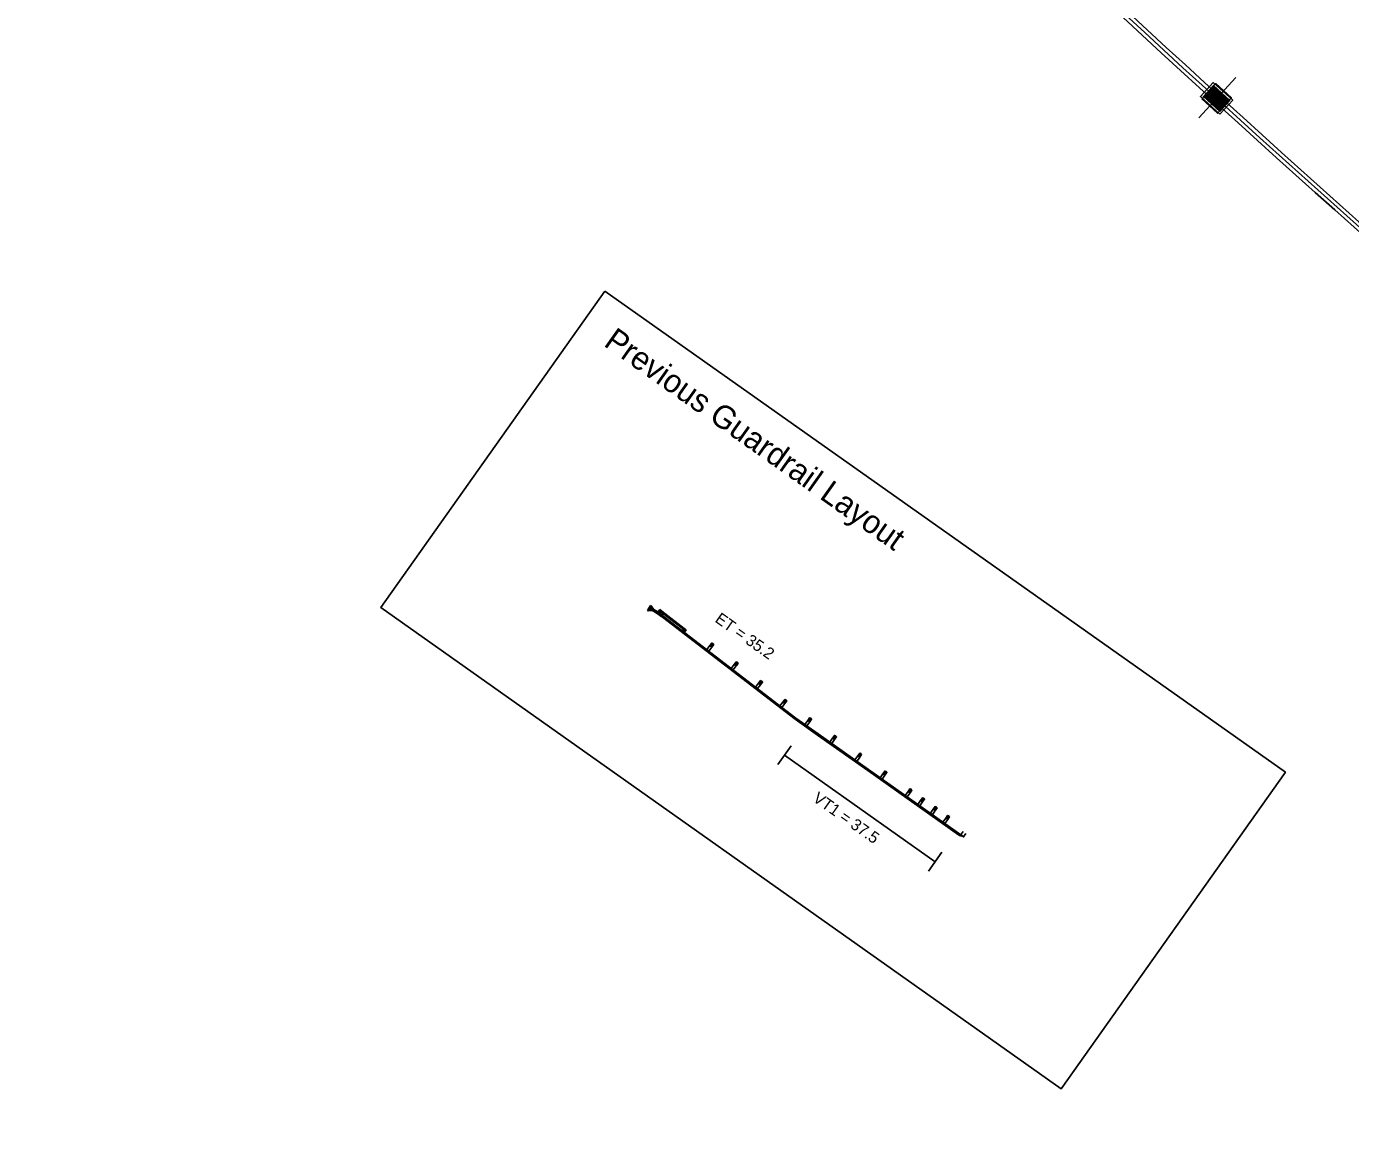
# Model space of a CAD drawing. Extents: x 16457860 to 16462445, y 6896068 to 6900243.
# Drawn here: x 16458321.9 to 16458590.6, y 6899787.1 to 6900015.1 of the extents above; entities that cross this region are included whole.
import ezdxf

# ---------------------------------------------------------------- set-up
doc = ezdxf.new("R2010")
doc.units = 0
for name, color, linetype in [('Barrier', 7, 'Continuous'), ('Draft_DNC', 7, 'Continuous'), ('RD Culv Reinf Concrete Sewer Pipe', 7, 'Continuous')]:
    doc.layers.add(name, color=color, linetype=linetype)

msp = doc.modelspace()

# ---------------------------------------------------------------- linework, layer by layer
at = {"layer": 'Barrier'}
for p, q in [((16458449.51, 6899896.2), (16458450.56, 6899895.5)), ((16458450.74, 6899895.76), (16458449.69, 6899896.47)), ((16458450.08, 6899895.89), (16458450.25, 6899896.1)), ((16458450.08, 6899895.89), (16458477.88, 6899874.47)), ((16458450.13, 6899896.19), (16458450.14, 6899896.2)), ((16458450.25, 6899896.1), (16458478.01, 6899874.71)), ((16458450.27, 6899896.11), (16458450.62, 6899896.57)), ((16458450.32, 6899895.66), (16458450.5, 6899895.92)), ((16458450.83, 6899896.4), (16458455.36, 6899892.91)), ((16458455.1, 6899892.36), (16458455.4, 6899892.13)), ((16458455.21, 6899892.28), (16458455.57, 6899892.75)), ((16458461.37, 6899889.63), (16458460.57, 6899889.41)), ((16458460.77, 6899889.26), (16458461.18, 6899889.79)), ((16458460.98, 6899889.94), (16458460.97, 6899889.1)), ((16458461.24, 6899889.86), (16458461.24, 6899889.87)), ((16458462.47, 6899886.34), (16458462.63, 6899886.56)), ((16458466.32, 6899885.82), (16458465.52, 6899885.6)), ((16458465.72, 6899885.44), (16458466.13, 6899885.97)), ((16458465.93, 6899886.12), (16458465.92, 6899885.29)), ((16458466.19, 6899886.05), (16458466.19, 6899886.05)), ((16458471.28, 6899882), (16458470.47, 6899881.78)), ((16458470.67, 6899881.63), (16458471.08, 6899882.16)), ((16458470.88, 6899882.31), (16458470.87, 6899881.48)), ((16458471.11, 6899882.13), (16458471.12, 6899882.13)), ((16458471.14, 6899882.23), (16458471.14, 6899882.24)), ((16458472.37, 6899878.71), (16458472.53, 6899878.93)), ((16458476.23, 6899878.19), (16458475.42, 6899877.97)), ((16458475.62, 6899877.81), (16458476.03, 6899878.34)), ((16458475.83, 6899878.49), (16458475.82, 6899877.66)), ((16458476.09, 6899878.42), (16458476.09, 6899878.42)), ((16458477.88, 6899874.47), (16458482.42, 6899871.26)), ((16458478.01, 6899874.71), (16458482.57, 6899871.48)), ((16458480.44, 6899874.24), (16458479.86, 6899873.43)), ((16458479.86, 6899873.43), (16458480.26, 6899873.12)), ((16458480.26, 6899873.12), (16458480.85, 6899873.95)), ((16458481.23, 6899874.5), (16458480.44, 6899874.24)), ((16458480.85, 6899873.95), (16458480.44, 6899874.24)), ((16458480.64, 6899874.1), (16458481.03, 6899874.64)), ((16458480.82, 6899874.78), (16458480.85, 6899873.95)), ((16458482.42, 6899871.26), (16458482.57, 6899871.48)), ((16458482.42, 6899871.26), (16458482.57, 6899871.48)), ((16458492.62, 6899864.04), (16458482.42, 6899871.26)), ((16458492.78, 6899864.26), (16458482.57, 6899871.48)), ((16458485.5, 6899870.64), (16458484.92, 6899869.82)), ((16458486.29, 6899870.89), (16458485.5, 6899870.64)), ((16458485.91, 6899870.35), (16458485.5, 6899870.64)), ((16458485.7, 6899870.49), (16458486.09, 6899871.04)), ((16458485.88, 6899871.18), (16458485.91, 6899870.35)), ((16458486.14, 6899871.11), (16458486.15, 6899871.12)), ((16458484.92, 6899869.82), (16458485.33, 6899869.53)), ((16458485.33, 6899869.53), (16458485.91, 6899870.35)), ((16458490.6, 6899867.03), (16458490.02, 6899866.21)), ((16458490.02, 6899866.21), (16458490.43, 6899865.92)), ((16458490.43, 6899865.92), (16458491.01, 6899866.74)), ((16458491.39, 6899867.28), (16458490.6, 6899867.03)), ((16458491.01, 6899866.74), (16458490.6, 6899867.03)), ((16458490.81, 6899866.88), (16458491.19, 6899867.43)), ((16458490.99, 6899867.57), (16458491.01, 6899866.74)), ((16458491.25, 6899867.51), (16458491.25, 6899867.51)), ((16458492.62, 6899864.04), (16458492.78, 6899864.26)), ((16458492.62, 6899864.04), (16458492.78, 6899864.26)), ((16458511.05, 6899851), (16458492.62, 6899864.04)), ((16458512.18, 6899850.53), (16458492.78, 6899864.26)), ((16458495.7, 6899863.42), (16458495.13, 6899862.6)), ((16458495.13, 6899862.6), (16458495.53, 6899862.31)), ((16458495.53, 6899862.31), (16458496.11, 6899863.13)), ((16458496.5, 6899863.67), (16458495.7, 6899863.42)), ((16458496.11, 6899863.13), (16458495.7, 6899863.42)), ((16458495.91, 6899863.27), (16458496.29, 6899863.82)), ((16458496.09, 6899863.96), (16458496.11, 6899863.13)), ((16458496.35, 6899863.9), (16458496.35, 6899863.9)), ((16458500.81, 6899859.81), (16458500.23, 6899858.99)), ((16458501.6, 6899860.06), (16458500.81, 6899859.81)), ((16458501.21, 6899859.52), (16458500.81, 6899859.81)), ((16458501.01, 6899859.66), (16458501.4, 6899860.21)), ((16458501.19, 6899860.35), (16458501.21, 6899859.52)), ((16458501.45, 6899860.29), (16458501.46, 6899860.29)), ((16458500.23, 6899858.99), (16458500.64, 6899858.7)), ((16458500.64, 6899858.7), (16458501.21, 6899859.52)), ((16458503.36, 6899858), (16458502.78, 6899857.18)), ((16458502.78, 6899857.18), (16458503.19, 6899856.9)), ((16458503.19, 6899856.9), (16458503.76, 6899857.71)), ((16458503.36, 6899858), (16458504.15, 6899858.26)), ((16458503.76, 6899857.71), (16458503.36, 6899858)), ((16458503.56, 6899857.86), (16458503.95, 6899858.4)), ((16458503.76, 6899857.71), (16458503.74, 6899858.54)), ((16458503.74, 6899858.54), (16458504.15, 6899858.26)), ((16458503.88, 6899858.45), (16458503.89, 6899858.46)), ((16458503.89, 6899858.46), (16458504.02, 6899858.37)), ((16458503.92, 6899858.44), (16458503.94, 6899858.47)), ((16458503.94, 6899858.47), (16458504.01, 6899858.42)), ((16458503.94, 6899858.43), (16458503.96, 6899858.46)), ((16458503.97, 6899858.45), (16458503.99, 6899858.47)), ((16458503.97, 6899858.4), (16458504, 6899858.43)), ((16458503.98, 6899858.44), (16458504, 6899858.46)), ((16458503.99, 6899858.47), (16458504, 6899858.46)), ((16458503.99, 6899858.39), (16458504.01, 6899858.42)), ((16458504.01, 6899858.35), (16458504.02, 6899858.37)), ((16458505.91, 6899856.2), (16458505.33, 6899855.38)), ((16458505.33, 6899855.38), (16458505.74, 6899855.09)), ((16458505.74, 6899855.09), (16458506.32, 6899855.91)), ((16458505.91, 6899856.2), (16458506.7, 6899856.45)), ((16458506.32, 6899855.91), (16458505.91, 6899856.2)), ((16458506.11, 6899856.05), (16458506.5, 6899856.6)), ((16458506.32, 6899855.91), (16458506.29, 6899856.74)), ((16458506.29, 6899856.74), (16458506.7, 6899856.45)), ((16458506.43, 6899856.64), (16458506.44, 6899856.66)), ((16458506.44, 6899856.66), (16458506.57, 6899856.56)), ((16458506.47, 6899856.63), (16458506.5, 6899856.66)), ((16458506.49, 6899856.62), (16458506.51, 6899856.65)), ((16458506.5, 6899856.66), (16458506.56, 6899856.62)), ((16458506.52, 6899856.65), (16458506.54, 6899856.67)), ((16458506.53, 6899856.6), (16458506.55, 6899856.63)), ((16458506.54, 6899856.67), (16458506.55, 6899856.66)), ((16458506.54, 6899856.63), (16458506.55, 6899856.66)), ((16458506.54, 6899856.59), (16458506.56, 6899856.62)), ((16458506.56, 6899856.55), (16458506.57, 6899856.56)), ((16458508.46, 6899854.39), (16458509.25, 6899854.65)), ((16458508.66, 6899854.25), (16458509.05, 6899854.79)), ((16458508.87, 6899854.1), (16458508.84, 6899854.94)), ((16458508.84, 6899854.94), (16458509.25, 6899854.65)), ((16458508.98, 6899854.84), (16458508.99, 6899854.85)), ((16458508.99, 6899854.85), (16458509.12, 6899854.76)), ((16458509.02, 6899854.83), (16458509.05, 6899854.86)), ((16458509.04, 6899854.82), (16458509.06, 6899854.85)), ((16458509.05, 6899854.86), (16458509.11, 6899854.81)), ((16458509.07, 6899854.84), (16458509.09, 6899854.86)), ((16458509.08, 6899854.79), (16458509.1, 6899854.82)), ((16458509.09, 6899854.86), (16458509.1, 6899854.85)), ((16458509.09, 6899854.83), (16458509.1, 6899854.85)), ((16458509.09, 6899854.78), (16458509.11, 6899854.81)), ((16458509.11, 6899854.74), (16458509.12, 6899854.76)), ((16458508.46, 6899854.39), (16458507.88, 6899853.58)), ((16458507.88, 6899853.58), (16458508.29, 6899853.29)), ((16458508.29, 6899853.29), (16458508.87, 6899854.1)), ((16458508.87, 6899854.1), (16458508.46, 6899854.39)), ((16458509.99, 6899851.75), (16458510.14, 6899851.97)), ((16458510.48, 6899851.4), (16458510.64, 6899851.63)), ((16458510.48, 6899851.4), (16458510.64, 6899851.63)), ((16458510.97, 6899851.06), (16458511.13, 6899851.28)), ((16458511.96, 6899851.66), (16458511.38, 6899850.84)), ((16458511.48, 6899850.81), (16458511.63, 6899850.77)), ((16458511.97, 6899850.65), (16458512.17, 6899850.51)), ((16458512.51, 6899851.27), (16458512.03, 6899850.61)), ((16458512.18, 6899850.53), (16458512.17, 6899850.51))]:
    msp.add_line(p, q, dxfattribs=at)
for points in [[(16458448.52, 6899897.57), (16458447.92, 6899896.57)], [(16458447.93, 6899896.58), (16458448.06, 6899896.5), (16458448.65, 6899897.48), (16458448.52, 6899897.56)], [(16458448.07, 6899896.48), (16458448.67, 6899897.49)], [(16458448.67, 6899897.49), (16458448.52, 6899897.57)], [(16458449.14, 6899896.8), (16458448.67, 6899897.49)], [(16458448.07, 6899896.48), (16458447.92, 6899896.57)], [(16458448.95, 6899896.52), (16458448.07, 6899896.48)], [(16458449.5, 6899896.19), (16458448.31, 6899896.9)], [(16458449.69, 6899896.47), (16458448.49, 6899897.19)], [(16458450.74, 6899895.77), (16458449.69, 6899896.47), (16458449.5, 6899896.19), (16458450.55, 6899895.49)], [(16458450.07, 6899896.26), (16458450.42, 6899896.72)], [(16458450.07, 6899896.26), (16458450.82, 6899896.42)], [(16458450.07, 6899896.26), (16458450.47, 6899895.95)], [(16458450.46, 6899895.94), (16458450.13, 6899896.19)], [(16458450.47, 6899895.95), (16458450.14, 6899896.2)], [(16458450.47, 6899895.95), (16458450.42, 6899896.72)], [(16458450.42, 6899896.72), (16458450.82, 6899896.42)], [(16458450.47, 6899895.96), (16458450.5, 6899895.99)], [(16458450.49, 6899895.95), (16458450.51, 6899895.98)], [(16458450.51, 6899896.68), (16458450.5, 6899896.67)], [(16458450.82, 6899896.42), (16458450.5, 6899896.67)], [(16458450.5, 6899895.99), (16458450.51, 6899896)], [(16458450.83, 6899896.43), (16458450.51, 6899896.68)], [(16458450.51, 6899896), (16458450.68, 6899896.23)], [(16458450.51, 6899895.98), (16458450.52, 6899895.99)], [(16458450.52, 6899895.99), (16458450.7, 6899896.22)], [(16458450.55, 6899895.49), (16458450.76, 6899895.35), (16458450.95, 6899895.63), (16458450.74, 6899895.77)], [(16458450.68, 6899896.23), (16458450.82, 6899896.41)], [(16458450.7, 6899896.22), (16458450.84, 6899896.4)], [(16458450.71, 6899896.24), (16458455.24, 6899892.75)], [(16458450.71, 6899896.23), (16458455.23, 6899892.75)], [(16458450.84, 6899896.4), (16458455.36, 6899892.91)], [(16458455.01, 6899892.46), (16458455.03, 6899892.49)], [(16458455.01, 6899892.43), (16458455.41, 6899892.13)], [(16458455.02, 6899892.45), (16458455.77, 6899892.6)], [(16458455.02, 6899892.45), (16458455.05, 6899892.48)], [(16458455.02, 6899892.45), (16458455.42, 6899892.14)], [(16458455.03, 6899892.49), (16458455.36, 6899892.91)], [(16458455.05, 6899892.48), (16458455.37, 6899892.91)], [(16458455.42, 6899892.14), (16458455.37, 6899892.91)], [(16458455.37, 6899892.91), (16458455.77, 6899892.6)], [(16458455.39, 6899892.92), (16458455.78, 6899892.61)], [(16458455.41, 6899892.13), (16458455.78, 6899892.61)], [(16458461.2, 6899889.77), (16458461.23, 6899889.8), (16458461.18, 6899889.84), (16458461.15, 6899889.81)], [(16458461.22, 6899889.81), (16458461.25, 6899889.85), (16458461.22, 6899889.87), (16458461.19, 6899889.83)], [(16458466.15, 6899885.95), (16458466.18, 6899885.98), (16458466.13, 6899886.03), (16458466.1, 6899885.99)], [(16458466.17, 6899885.99), (16458466.2, 6899886.04), (16458466.17, 6899886.06), (16458466.14, 6899886.02)], [(16458471.1, 6899882.14), (16458471.13, 6899882.17), (16458471.08, 6899882.21), (16458471.05, 6899882.18)], [(16458471.12, 6899882.18), (16458471.15, 6899882.22), (16458471.12, 6899882.25), (16458471.09, 6899882.2)], [(16458476.05, 6899878.32), (16458476.08, 6899878.36), (16458476.03, 6899878.4), (16458476, 6899878.36)], [(16458476.07, 6899878.36), (16458476.1, 6899878.41), (16458476.07, 6899878.43), (16458476.04, 6899878.39)], [(16458481.06, 6899874.62), (16458481.08, 6899874.66), (16458481.03, 6899874.69), (16458481, 6899874.66)], [(16458481.07, 6899874.66), (16458481.1, 6899874.71), (16458481.07, 6899874.73), (16458481.04, 6899874.69)], [(16458486.12, 6899871.02), (16458486.14, 6899871.05), (16458486.09, 6899871.09), (16458486.06, 6899871.05)], [(16458486.13, 6899871.06), (16458486.16, 6899871.1), (16458486.13, 6899871.13), (16458486.1, 6899871.08)], [(16458491.22, 6899867.41), (16458491.24, 6899867.44), (16458491.19, 6899867.48), (16458491.16, 6899867.45)], [(16458491.23, 6899867.45), (16458491.26, 6899867.49), (16458491.23, 6899867.52), (16458491.2, 6899867.47)], [(16458496.32, 6899863.8), (16458496.35, 6899863.83), (16458496.29, 6899863.87), (16458496.27, 6899863.84)], [(16458496.33, 6899863.84), (16458496.37, 6899863.88), (16458496.33, 6899863.91), (16458496.3, 6899863.86)], [(16458501.42, 6899860.19), (16458501.45, 6899860.22), (16458501.39, 6899860.26), (16458501.37, 6899860.23)], [(16458501.44, 6899860.23), (16458501.47, 6899860.27), (16458501.44, 6899860.3), (16458501.4, 6899860.25)]]:
    msp.add_lwpolyline(points, dxfattribs=at)
for points in [[(16458450.74, 6899895.77), (16458450.76, 6899895.8), (16458450.97, 6899895.66), (16458450.95, 6899895.63), (16458450.76, 6899895.35), (16458450.74, 6899895.32), (16458450.53, 6899895.46), (16458450.55, 6899895.49)], [(16458460.36, 6899888.31), (16458459.96, 6899888.62), (16458460.57, 6899889.41), (16458460.97, 6899889.1)], [(16458460.97, 6899889.1), (16458460.57, 6899889.41), (16458460.98, 6899889.94), (16458461.37, 6899889.63)], [(16458465.31, 6899884.5), (16458464.91, 6899884.8), (16458465.52, 6899885.6), (16458465.92, 6899885.29)], [(16458465.92, 6899885.29), (16458465.52, 6899885.6), (16458465.93, 6899886.12), (16458466.32, 6899885.82)], [(16458470.26, 6899880.68), (16458469.86, 6899880.99), (16458470.47, 6899881.78), (16458470.87, 6899881.48)], [(16458470.87, 6899881.48), (16458470.47, 6899881.78), (16458470.88, 6899882.31), (16458471.28, 6899882)], [(16458475.21, 6899876.87), (16458474.81, 6899877.17), (16458475.42, 6899877.97), (16458475.82, 6899877.66)], [(16458475.82, 6899877.66), (16458475.42, 6899877.97), (16458475.83, 6899878.49), (16458476.23, 6899878.19)], [(16458480.85, 6899873.95), (16458480.44, 6899874.24), (16458480.82, 6899874.78), (16458481.23, 6899874.5)], [(16458485.91, 6899870.35), (16458485.5, 6899870.64), (16458485.88, 6899871.18), (16458486.29, 6899870.89)], [(16458491.01, 6899866.74), (16458490.6, 6899867.03), (16458490.99, 6899867.57), (16458491.39, 6899867.28)], [(16458496.11, 6899863.13), (16458495.7, 6899863.42), (16458496.09, 6899863.96), (16458496.5, 6899863.67)], [(16458501.21, 6899859.52), (16458500.81, 6899859.81), (16458501.19, 6899860.35), (16458501.6, 6899860.06)], [(16458503.76, 6899857.71), (16458503.36, 6899858), (16458503.74, 6899858.54), (16458504.15, 6899858.26)], [(16458506.32, 6899855.91), (16458505.91, 6899856.2), (16458506.29, 6899856.74), (16458506.7, 6899856.45)], [(16458508.87, 6899854.1), (16458508.46, 6899854.39), (16458508.84, 6899854.94), (16458509.25, 6899854.65)]]:
    msp.add_lwpolyline(points, close=True, dxfattribs=at)
for centre, radius, start, end in [((16458450.47, 6899895.96), 0.0208, 232.3781, 322.3781), ((16458450.47, 6899895.96), 0.00517, 232.3781, 322.3781), ((16458450.82, 6899896.41), 0.00517, 322.3781, 52.3781), ((16458450.82, 6899896.41), 0.0208, 322.3781, 52.3781), ((16458455.03, 6899892.45), 0.0208, 142.3781, 232.3781), ((16458455.37, 6899892.9), 0.0208, 52.3781, 142.3781)]:
    msp.add_arc(centre, radius, start, end, dxfattribs=at)
for centre, major_axis, start_param, end_param in [((16458511.85, 6899852.27), (1.26, -0.89), 4.763936, 5.071137), ((16458511.37, 6899849.45), (-1.13, 0.8), 4.866664, 5.124351)]:
    msp.add_ellipse(centre, major_axis=major_axis, ratio=0.97085, start_param=start_param, end_param=end_param, dxfattribs=at)
at = {"layer": 'Draft_DNC'}
for p, q in [((16458559.84, 6899996.59), (16458567.29, 6900004.77)), ((16458474.39, 6899865.25), (16458477.1, 6899869.08)), ((16458506.33, 6899845.53), (16458475.74, 6899867.17)), ((16458504.97, 6899843.62), (16458507.68, 6899847.45))]:
    msp.add_line(p, q, dxfattribs=at)
for points in [[(16458560.4, 6900000.42), (16458563.6, 6899997.5), (16458566.44, 6900000.61), (16458563.23, 6900003.53)], [(16458561.34, 6900000.46), (16458563.56, 6899998.44), (16458565.49, 6900000.57), (16458563.28, 6900002.59)], [(16458439.3, 6899961.39), (16458577.37, 6899863.71), (16458531.91, 6899799.46), (16458393.84, 6899897.14)]]:
    msp.add_lwpolyline(points, close=True, dxfattribs=at)
for radius in [3510.85, 3510.1, 3509.35]:
    msp.add_arc((16460928.02, 6902594.63), radius, 222.07208, 233.09848, dxfattribs=at)
at = {"layer": 'RD Culv Reinf Concrete Sewer Pipe'}
for p, q in [((16458565.26, 6899999.57), (16458562.3, 6900002.26)), ((16458565.32, 6899999.63), (16458562.36, 6900002.32)), ((16458565.39, 6899999.71), (16458562.43, 6900002.4)), ((16458565.44, 6899999.77), (16458562.49, 6900002.46)), ((16458565.51, 6899999.84), (16458562.56, 6900002.54)), ((16458565.57, 6899999.91), (16458562.61, 6900002.6)), ((16458565.64, 6899999.98), (16458562.68, 6900002.68)), ((16458565.7, 6900000.05), (16458562.74, 6900002.74)), ((16458564.56, 6899998.8), (16458561.6, 6900001.49)), ((16458564.63, 6899998.87), (16458561.67, 6900001.57)), ((16458564.69, 6899998.94), (16458561.73, 6900001.63)), ((16458564.76, 6899999.01), (16458561.8, 6900001.71)), ((16458564.81, 6899999.07), (16458561.85, 6900001.77)), ((16458564.88, 6899999.15), (16458561.92, 6900001.84)), ((16458564.94, 6899999.21), (16458561.98, 6900001.91)), ((16458565.01, 6899999.29), (16458562.05, 6900001.98)), ((16458565.06, 6899999.35), (16458562.11, 6900002.04)), ((16458565.13, 6899999.43), (16458562.18, 6900002.12)), ((16458565.19, 6899999.49), (16458562.23, 6900002.18)), ((16458562.53, 6899999.63), (16458562.6, 6899999.71)), ((16458562.62, 6899999.55), (16458562.69, 6899999.62)), ((16458562.66, 6899999.77), (16458562.73, 6899999.85)), ((16458562.75, 6899999.69), (16458562.82, 6899999.76)), ((16458562.78, 6899999.91), (16458562.85, 6899999.99)), ((16458562.87, 6899999.82), (16458562.94, 6899999.9)), ((16458562.91, 6900000.05), (16458562.98, 6900000.12)), ((16458563, 6899999.96), (16458563.07, 6900000.04)), ((16458563.03, 6900000.19), (16458563.1, 6900000.26)), ((16458563.13, 6900000.1), (16458563.2, 6900000.18)), ((16458563.16, 6900000.32), (16458563.23, 6900000.4)), ((16458563.25, 6900000.24), (16458563.32, 6900000.32)), ((16458563.29, 6900000.46), (16458563.36, 6900000.54)), ((16458563.38, 6900000.38), (16458563.45, 6900000.46)), ((16458563.41, 6900000.6), (16458563.48, 6900000.68)), ((16458563.51, 6900000.52), (16458563.58, 6900000.59)), ((16458563.54, 6900000.74), (16458563.61, 6900000.82)), ((16458563.63, 6900000.66), (16458563.7, 6900000.73)), ((16458563.67, 6900000.88), (16458563.74, 6900000.96)), ((16458563.76, 6900000.79), (16458563.83, 6900000.87)), ((16458563.79, 6900001.02), (16458563.86, 6900001.09)), ((16458563.88, 6900000.93), (16458563.95, 6900001.01)), ((16458563.92, 6900001.16), (16458563.99, 6900001.23)), ((16458564.01, 6900001.07), (16458564.08, 6900001.15)), ((16458564.04, 6900001.3), (16458564.11, 6900001.37)), ((16458564.14, 6900001.21), (16458564.21, 6900001.29)), ((16458564.17, 6900001.43), (16458564.21, 6900001.48)), ((16458564.26, 6900001.35), (16458564.3, 6900001.4))]:
    msp.add_line(p, q, dxfattribs=at)
for points in [[(16458564.1, 6899997.3), (16458560.15, 6900000.89), (16458562.74, 6900003.73), (16458566.68, 6900000.14)], [(16458564.07, 6899997.89), (16458560.74, 6900000.92), (16458562.76, 6900003.14), (16458566.09, 6900000.11)], [(16458564.06, 6899998.04), (16458560.89, 6900000.93), (16458562.77, 6900002.99), (16458565.94, 6900000.1)], [(16458565.19, 6899999.49), (16458562.23, 6900002.18), (16458562.3, 6900002.26), (16458565.26, 6899999.57)], [(16458565.32, 6899999.63), (16458562.36, 6900002.32), (16458562.43, 6900002.4), (16458565.39, 6899999.71)], [(16458565.44, 6899999.77), (16458562.49, 6900002.46), (16458562.56, 6900002.54), (16458565.51, 6899999.84)], [(16458565.57, 6899999.91), (16458562.61, 6900002.6), (16458562.68, 6900002.68), (16458565.64, 6899999.98)], [(16458565.7, 6900000.05), (16458562.74, 6900002.74), (16458562.78, 6900002.78), (16458565.74, 6900000.09)], [(16458564.05, 6899998.24), (16458561.1, 6900000.94), (16458561.17, 6900001.01), (16458564.12, 6899998.32)], [(16458564.18, 6899998.38), (16458561.22, 6900001.07), (16458561.29, 6900001.15), (16458564.25, 6899998.46)], [(16458564.31, 6899998.52), (16458561.35, 6900001.21), (16458561.42, 6900001.29), (16458564.38, 6899998.6)], [(16458564.43, 6899998.66), (16458561.48, 6900001.35), (16458561.55, 6900001.43), (16458564.5, 6899998.74)], [(16458564.56, 6899998.8), (16458561.6, 6900001.49), (16458561.67, 6900001.57), (16458564.63, 6899998.87)], [(16458564.69, 6899998.94), (16458561.73, 6900001.63), (16458561.8, 6900001.71), (16458564.76, 6899999.01)], [(16458564.81, 6899999.07), (16458561.85, 6900001.77), (16458561.92, 6900001.84), (16458564.88, 6899999.15)], [(16458564.94, 6899999.21), (16458561.98, 6900001.91), (16458562.05, 6900001.98), (16458565.01, 6899999.29)], [(16458565.06, 6899999.35), (16458562.11, 6900002.04), (16458562.18, 6900002.12), (16458565.13, 6899999.43)]]:
    msp.add_lwpolyline(points, close=True, dxfattribs=at)

# ---------------------------------------------------------------- texts
at = {"layer": 'Draft_DNC'}
for s, height, p in [('Previous Guardrail Layout', 4.6875, (16458438.84, 6899950.41)), ('ET = 35.2', 2.344, (16458461.45, 6899894.37)), ('VT1 = 37.5', 2.344, (16458481.31, 6899857.97))]:
    msp.add_text(s, height=height, rotation=324.7216, dxfattribs=at).set_placement(p)

doc.saveas('drawing.dxf')
